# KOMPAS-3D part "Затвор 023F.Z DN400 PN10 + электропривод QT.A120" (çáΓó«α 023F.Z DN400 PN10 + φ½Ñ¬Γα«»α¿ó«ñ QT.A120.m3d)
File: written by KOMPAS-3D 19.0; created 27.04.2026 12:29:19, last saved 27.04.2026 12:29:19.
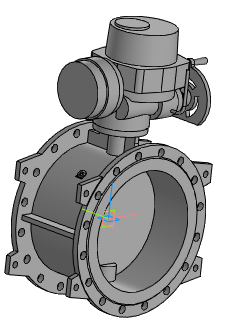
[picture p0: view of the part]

Document properties: Полное имя файла: Затвор 023F.Z DN400 PN10 + электропривод QT.A120.a3d

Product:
- Part/product: Затвор 023F.Z DN400 PN10 + электропривод QT.A120
    Масса: 282.946

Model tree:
1. Операция без истории:1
